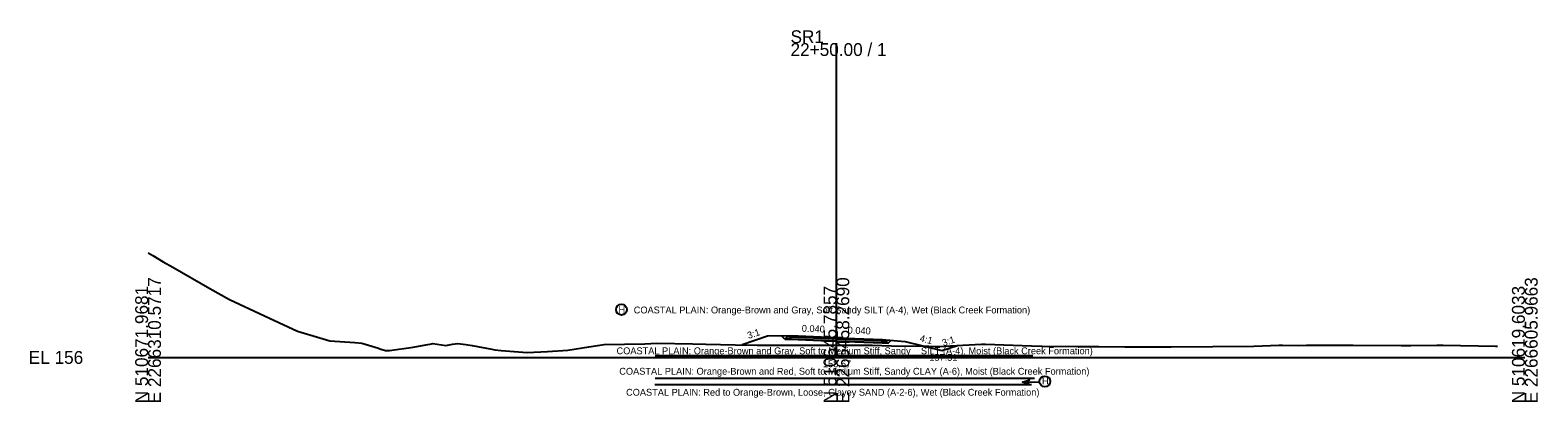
# Model space of a CAD drawing. Extents: x -1079 to 303, y -11 to 4017.
# Drawn here: x -25.7 to 302.8, y 1490.3 to 1571.4 of the extents above; entities that cross this region are included whole.
import ezdxf

# ---------------------------------------------------------------- set-up
doc = ezdxf.new("R2010")
doc.units = 0
for name, color, linetype in [('Default', 7, 'Continuous'), ('Exist Cross Section Cell', 7, 'Continuous'), ('Exist XS Center Line Elevation Label', 7, 'Continuous'), ('Exist XS Ground Line', 7, 'Continuous'), ('Misc Plan Tools Cell', 7, 'Continuous'), ('Prop CMT Pvmt Course 1', 7, 'Continuous'), ('Prop CMT Pvmt Course 2', 7, 'Continuous'), ('Prop CMT Pvmt Course 3', 7, 'Continuous'), ('Prop CMT Pvmt Surface', 7, 'Continuous'), ('Prop CMT Pvmt Surface Shoulder', 7, 'Continuous'), ('Prop CMT Shld Paved Course 1', 7, 'Continuous'), ('Prop CMT Shld Paved Course 2', 7, 'Continuous'), ('Prop CMT Shld Paved Course 3', 7, 'Continuous'), ('Prop CMT Slope Grass', 7, 'Continuous'), ('Prop CMT Subgrade Earthwork', 7, 'Continuous'), ('Prop Road Sect_ Material - Bubble + Leader + Bubble Tx', 7, 'Continuous'), ('Prop Road Sect_ Material - Contact (General - Minor)', 7, 'Continuous'), ('Prop Road Sect_ Material - Tx (Composite Desc)', 7, 'Continuous'), ('Prop XS Ditch Standard Text', 7, 'Continuous'), ('Prop XS SE Text', 7, 'Continuous'), ('Prop XS Side Slope Text', 7, 'Continuous')]:
    doc.layers.add(name, color=color, linetype=linetype)

msp = doc.modelspace()

# ---------------------------------------------------------------- linework, layer by layer
at = {"layer": 'Exist Cross Section Cell'}
for p, q in [((150, 1500), (150, 1568.55)), ((0, 1500), (150, 1500)), ((150, 1500), (300, 1500))]:
    msp.add_line(p, q, dxfattribs=at)
at = {"layer": 'Exist XS Ground Line'}
msp.add_lwpolyline([(0, 1522.85), (1.01, 1522.22), (3.27, 1520.86), (5.42, 1519.7), (13.45, 1515.05), (17.73, 1512.61), (26.43, 1508.53), (32.56, 1505.73), (37.45, 1504.25), (39.6, 1503.63), (45.08, 1503.28), (46.58, 1503.08), (50.19, 1502.03), (50.51, 1501.9), (51.72, 1501.54), (52.64, 1501.54), (57.79, 1502.22), (59.71, 1502.57), (60.97, 1502.82), (61.47, 1502.92), (62.05, 1503.02), (63.03, 1502.88), (64.92, 1502.57), (66.35, 1502.86), (67.5, 1503.07), (69.22, 1502.84), (70.62, 1502.63), (74.88, 1501.79), (75.57, 1501.64), (76.96, 1501.52), (82.58, 1501.09), (87.06, 1501.27), (91.49, 1501.6), (96.06, 1502.34), (99.37, 1502.83), (108.28, 1503), (110.86, 1503.08), (118.62, 1502.94), (121.55, 1502.9), (127.94, 1502.78), (132.72, 1502.7), (138.98, 1502.66), (147.71, 1502.7), (150, 1502.67), (151.87, 1502.65), (157.81, 1502.64), (162.02, 1502.54), (170.16, 1502.45), (172.18, 1502.42), (181.58, 1502.9), (182.5, 1502.93), (192.5, 1502.5), (194.85, 1502.47), (202.65, 1502.36), (207.19, 1502.39), (212.81, 1502.34), (219.54, 1502.28), (222.97, 1502.28), (232.03, 1502.38), (240.98, 1502.45), (246.38, 1502.65), (247.17, 1502.68), (250.71, 1502.59), (252.43, 1502.66), (255.63, 1502.7), (261.03, 1502.71), (261.95, 1502.71), (262.58, 1502.71), (273.04, 1502.61), (275.14, 1502.6), (280.84, 1502.65), (282.22, 1502.67), (293.61, 1502.49), (294.07, 1502.48)], dxfattribs=at)
at = {"layer": 'Misc Plan Tools Cell'}
msp.add_lwpolyline([(192.03, 1494.08), (190.53, 1494.59), (192.04, 1495.08), (191.53, 1494.58)], close=True, dxfattribs=at)
at = {"layer": 'Prop CMT Pvmt Course 1'}
for points in [[(150, 1504.31), (140, 1504.71)], [(140, 1504.71), (140, 1504.46)], [(140, 1504.46), (150, 1504.06)], [(150, 1504.06), (150, 1504.31)], [(150, 1504.31), (160, 1503.91)], [(150, 1504.06), (150, 1504.31)], [(160, 1503.66), (150, 1504.06)], [(160, 1503.91), (160, 1503.66)]]:
    msp.add_lwpolyline(points, dxfattribs=at)
msp.add_lwpolyline([(150, 1504.06), (150, 1504.19), (150, 1504.19), (150, 1504.06)], close=True, dxfattribs=at)
msp.add_lwpolyline([(150, 1504.06), (150, 1504.19), (150, 1504.19), (150, 1504.06)], close=True, dxfattribs=at)
at = {"layer": 'Prop CMT Pvmt Course 2'}
for points in [[(140, 1504.46), (150, 1504.06)], [(150, 1504.06), (140, 1504.46)], [(140, 1504.46), (140, 1504.46)], [(150, 1504.06), (150, 1504.06)], [(160, 1503.66), (150, 1504.06)], [(150, 1504.06), (150, 1504.06)], [(150, 1504.06), (160, 1503.66)], [(160, 1503.66), (160, 1503.66)]]:
    msp.add_lwpolyline(points, dxfattribs=at)
at = {"layer": 'Prop CMT Pvmt Course 3'}
for points in [[(150, 1504.06), (140, 1504.46)], [(140, 1504.46), (140, 1503.96)], [(140, 1503.96), (150, 1503.56)], [(150, 1503.56), (150, 1504.06)], [(150, 1504.06), (160, 1503.66)], [(150, 1503.56), (150, 1504.06)], [(160, 1503.16), (150, 1503.56)], [(160, 1503.66), (160, 1503.16)]]:
    msp.add_lwpolyline(points, dxfattribs=at)
at = {"layer": 'Prop CMT Pvmt Surface'}
for q in [(140, 1504.71), (160, 1503.91)]:
    msp.add_line((150, 1504.31), q, dxfattribs=at)
at = {"layer": 'Prop CMT Pvmt Surface Shoulder'}
for p, q in [((140, 1504.71), (140, 1504.71)), ((160, 1503.91), (160, 1503.91))]:
    msp.add_line(p, q, dxfattribs=at)
at = {"layer": 'Prop CMT Shld Paved Course 1'}
for points in [[(140, 1504.71), (140, 1504.71), (139.76, 1504.47)], [(140, 1504.46), (140, 1504.71)], [(139.76, 1504.47), (140, 1504.46)], [(160, 1503.91), (160, 1503.91), (160.26, 1503.65)], [(160, 1503.66), (160, 1503.91)], [(160.26, 1503.65), (160, 1503.66)]]:
    msp.add_lwpolyline(points, dxfattribs=at)
at = {"layer": 'Prop CMT Shld Paved Course 2'}
for points in [[(140, 1504.46), (139.76, 1504.47)], [(139.76, 1504.47), (139.76, 1504.47)], [(139.76, 1504.47), (140, 1504.46)], [(140, 1504.46), (140, 1504.46)], [(160, 1503.66), (160.26, 1503.65)], [(160.26, 1503.65), (160, 1503.66)], [(160, 1503.66), (160, 1503.66)], [(160.26, 1503.65), (160.26, 1503.65)]]:
    msp.add_lwpolyline(points, dxfattribs=at)
at = {"layer": 'Prop CMT Shld Paved Course 3'}
for points in [[(140, 1504.46), (139.76, 1504.47), (139.26, 1504.49), (138.78, 1504.01)], [(138.78, 1504.01), (140, 1503.96)], [(140, 1503.96), (140, 1504.46)], [(160, 1503.66), (160.26, 1503.65), (160.76, 1503.63), (161.28, 1503.11)], [(160, 1503.16), (160, 1503.66)], [(161.28, 1503.11), (160, 1503.16)]]:
    msp.add_lwpolyline(points, dxfattribs=at)
at = {"layer": 'Prop CMT Slope Grass'}
for p, q in [((140, 1504.71), (135, 1504.61)), ((135, 1504.61), (129.43, 1502.76)), ((160, 1503.91), (165, 1503.51)), ((165, 1503.51), (173, 1501.51)), ((173, 1501.51), (176.36, 1502.63))]:
    msp.add_line(p, q, dxfattribs=at)
at = {"layer": 'Prop CMT Subgrade Earthwork'}
for points in [[(138.78, 1504.01), (138.11, 1504.67)], [(140, 1503.96), (138.78, 1504.01)], [(150, 1503.56), (140, 1503.96)], [(150, 1503.56), (160, 1503.16)], [(160, 1503.16), (161.28, 1503.11)], [(161.28, 1503.11), (161.93, 1503.76)]]:
    msp.add_lwpolyline(points, dxfattribs=at)
at = {"layer": 'Prop Road Sect_ Material - Bubble + Leader + Bubble Tx'}
msp.add_line((194.24, 1494.56), (191.53, 1494.58), dxfattribs=at)
for centre in [(103.16, 1510.43), (195.42, 1494.77)]:
    msp.add_circle(centre, 1.18, dxfattribs=at)
at = {"layer": 'Prop Road Sect_ Material - Contact (General - Minor)'}
for p, q in [((110.47, 1500.4), (192.81, 1500.4)), ((110.5, 1495.5), (193.15, 1495.5)), ((192.51, 1494), (110.41, 1494))]:
    msp.add_line(p, q, dxfattribs=at)

# ---------------------------------------------------------------- texts
at = {"layer": 'Default'}
msp.add_text('-', height=0.0001, dxfattribs=at).set_placement((0, 1500))
at = {"layer": 'Exist Cross Section Cell'}
for s, p in [('SR1', (140, 1568.55)), ('22+50.00 / 1', (140, 1565.75)), ('EL 156', (-26, 1498.6))]:
    msp.add_text(s, height=2.8, dxfattribs=at).set_placement(p)
for s, p in [('N 510671.9681', (0, 1490)), ('E 2266310.5717', (2.8, 1490)), ('N 510645.7857', (150, 1490)), ('E 2266458.2690', (152.8, 1490)), ('N 510619.6033', (300, 1490)), ('E 2266605.9663', (302.8, 1490))]:
    msp.add_text(s, height=2.8, rotation=90, dxfattribs=at).set_placement(p)
at = {"layer": 'Exist XS Center Line Elevation Label'}
msp.add_text('158.67', height=1.5, dxfattribs=at).set_placement((147.06, 1497.87))
at = {"layer": 'Prop Road Sect_ Material - Tx (Composite Desc)'}
for s, p in [('H', (102.51, 1509.7)), ('COASTAL PLAIN: Orange-Brown and Gray, Soft Sandy SILT (A-4), Wet (Black Creek Formation)', (105.83, 1509.6)), ('COASTAL PLAIN: Orange-Brown and Gray, Soft to Medium Stiff, Sandy    SILT (A-4), Moist (Black Creek Formation)', (102.08, 1500.69)), ('COASTAL PLAIN: Orange-Brown and Red, Soft to Medium Stiff, Sandy CLAY (A-6), Moist (Black Creek Formation)', (102.68, 1496.23)), ('H', (194.78, 1494.1)), ('COASTAL PLAIN: Red to Orange-Brown, Loose, Clayey SAND (A-2-6), Wet (Black Creek Formation)', (104.16, 1491.65))]:
    msp.add_text(s, height=1.5, dxfattribs=at).set_placement(p)
at = {"layer": 'Prop XS Ditch Standard Text'}
msp.add_text('157.51', height=1.5, dxfattribs=at).set_placement((170.24, 1499.26))
at = {"layer": 'Prop XS SE Text'}
for p in [(142.42, 1505.62), (152.42, 1505.22)]:
    msp.add_text('0.040', height=1.5, rotation=357.7094, dxfattribs=at).set_placement(p)
at = {"layer": 'Prop XS Side Slope Text'}
for s, rotation, p in [('3:1', 18.4332, (130.85, 1504.02)), ('4:1', 345.9638, (168.03, 1503.53)), ('3:1', 18.4332, (173.31, 1502.41))]:
    msp.add_text(s, height=1.5, rotation=rotation, dxfattribs=at).set_placement(p)

doc.saveas('drawing.dxf')
